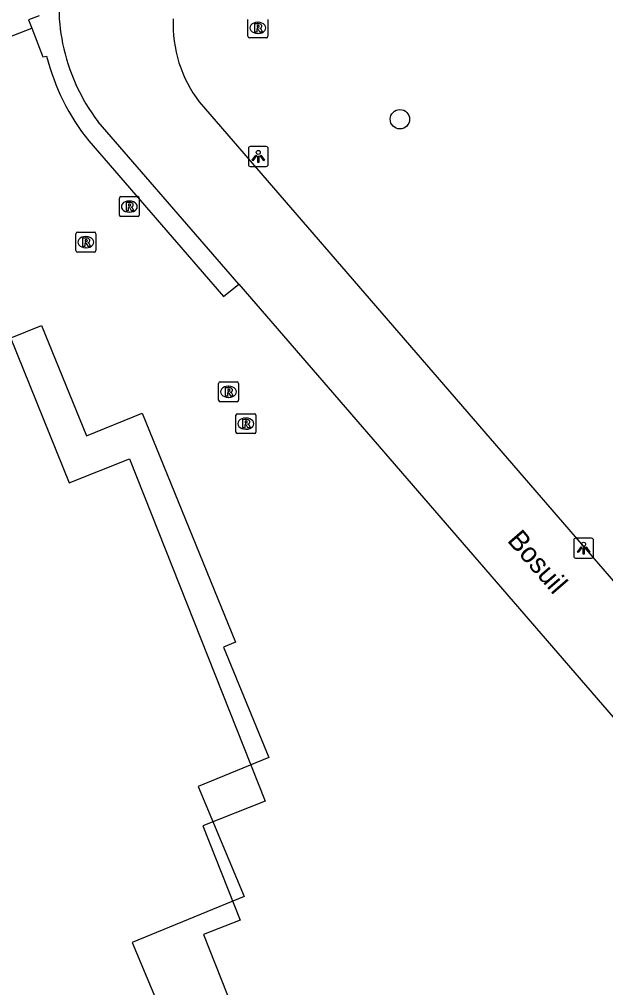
# Model space of a CAD drawing. Extents: x 156664 to 157568, y 383571 to 384421.
# Drawn here: x 156811.21 to 156840.66, y 383832.57 to 383881.24 of the extents above; entities that cross this region are included whole.
import ezdxf

# ---------------------------------------------------------------- set-up
doc = ezdxf.new("R2010")
doc.units = 0
for name, color, linetype in [('IMGEO_Berm_open', 7, 'Continuous'), ('IMGEO_Boom', 7, 'Continuous'), ('IMGEO_Groenvoorziening', 7, 'Continuous'), ('IMGEO_Lichtpunt', 7, 'Continuous'), ('IMGEO_Openbare_ruimte_label', 7, 'Continuous'), ('IMGEO_Pand', 7, 'Continuous'), ('IMGEO_Pand_vergunning_verleend', 7, 'Continuous'), ('IMGEO_Rijbaan_lokaal_open', 7, 'Continuous'), ('IMGEO_Rioolput', 7, 'Continuous')]:
    doc.layers.add(name, color=color, linetype=linetype)

msp = doc.modelspace()

# ---------------------------------------------------------------- linework, layer by layer
at = {"layer": 'IMGEO_Berm_open'}
for points in [[(156812.204, 383881.419), (156811.669, 383881.211), (156811.831, 383880.795)], [(156811.831, 383880.795), (156812.391, 383879.356), (156812.577, 383879.388)], [(156814.702, 383875.125), (156821.46, 383867.3), (156822.231, 383867.92)]]:
    msp.add_lwpolyline(points, dxfattribs=at)
msp.add_arc((156823.408, 383882.126), 11.171, 194.1855, 218.8047, dxfattribs=at)
at = {"layer": 'IMGEO_Boom'}
msp.add_circle((156830.325, 383876.218), 0.489, dxfattribs=at)
at = {"layer": 'IMGEO_Groenvoorziening'}
msp.add_lwpolyline([(156804.978, 383878.126), (156811.831, 383880.795)], dxfattribs=at)
at = {"layer": 'IMGEO_Lichtpunt'}
for p, q in [((156822.713, 383874.751), (156822.713, 383873.944)), ((156822.713, 383874.751), (156822.713, 383873.944)), ((156823.615, 383874.846), (156822.807, 383874.846)), ((156823.615, 383874.846), (156822.807, 383874.846)), ((156823.709, 383873.944), (156823.709, 383874.751)), ((156823.709, 383873.944), (156823.709, 383874.751)), ((156822.807, 383873.85), (156823.615, 383873.85)), ((156822.807, 383873.85), (156823.615, 383873.85)), ((156839.957, 383855.156), (156839.149, 383855.156)), ((156839.957, 383855.156), (156839.149, 383855.156)), ((156839.055, 383855.061), (156839.055, 383854.254)), ((156839.055, 383855.061), (156839.055, 383854.254)), ((156840.051, 383854.254), (156840.051, 383855.061)), ((156840.051, 383854.254), (156840.051, 383855.061)), ((156839.149, 383854.16), (156839.957, 383854.16)), ((156839.149, 383854.16), (156839.957, 383854.16))]:
    msp.add_line(p, q, dxfattribs=at)
for points in [[(156823.087, 383874.415), (156823.126, 383874.387), (156822.938, 383874.125), (156822.9, 383874.152), (156823.087, 383874.415)], [(156823.189, 383874.367), (156823.236, 383874.367), (156823.236, 383874.045), (156823.189, 383874.045), (156823.189, 383874.367)], [(156823.299, 383874.387), (156823.337, 383874.414), (156823.524, 383874.152), (156823.485, 383874.124), (156823.299, 383874.387)], [(156839.429, 383854.725), (156839.468, 383854.697), (156839.28, 383854.435), (156839.242, 383854.462), (156839.429, 383854.725)], [(156839.531, 383854.677), (156839.578, 383854.677), (156839.578, 383854.355), (156839.531, 383854.355), (156839.531, 383854.677)], [(156839.641, 383854.697), (156839.679, 383854.724), (156839.866, 383854.462), (156839.827, 383854.434), (156839.641, 383854.697)]]:
    msp.add_lwpolyline(points, dxfattribs=at)
for centre in [(156823.212, 383874.549), (156839.554, 383854.859)]:
    msp.add_circle(centre, 0.0994, dxfattribs=at)
for centre, start, end in [((156822.807, 383874.751), 90, 180), ((156822.807, 383874.751), 90, 180), ((156823.615, 383874.751), 0, 90), ((156823.615, 383874.751), 0, 90), ((156822.807, 383873.944), 180, 270), ((156822.807, 383873.944), 180, 270), ((156823.615, 383873.944), 270, 0), ((156823.615, 383873.944), 270, 360), ((156839.149, 383855.061), 90, 180), ((156839.149, 383855.061), 90, 180), ((156839.957, 383855.061), 0, 90), ((156839.957, 383855.061), 0, 90), ((156839.149, 383854.254), 180, 270), ((156839.149, 383854.254), 180, 270), ((156839.957, 383854.254), 270, 0), ((156839.957, 383854.254), 270, 360)]:
    msp.add_arc(centre, 0.0946, start, end, dxfattribs=at)
at = {"layer": 'IMGEO_Pand'}
msp.add_lwpolyline([(156810.752, 383865.212), (156812.318, 383865.856), (156814.59, 383860.304), (156817.377, 383861.45), (156822.064, 383849.936), (156821.462, 383849.689), (156823.742, 383844.139), (156820.198, 383842.684), (156822.503, 383837.144), (156816.871, 383834.832), (156818.054, 383832.045), (156811.056, 383829.074)], dxfattribs=at)
at = {"layer": 'IMGEO_Pand_vergunning_verleend'}
msp.add_lwpolyline([(156780.469, 383854.207), (156810.422, 383866.069), (156813.706, 383857.943), (156816.747, 383859.147), (156823.563, 383841.936), (156820.432, 383840.696), (156822.305, 383835.967), (156820.454, 383835.234), (156822.799, 383829.314), (156801.042, 383820.698), (156799.834, 383823.747), (156795.744, 383822.127), (156793.475, 383827.857), (156790.011, 383826.485), (156783.663, 383842.517), (156784.904, 383843.008), (156780.469, 383854.207)], dxfattribs=at)
at = {"layer": 'IMGEO_Rijbaan_lokaal_open'}
for points in [[(156820.249, 383877.085), (156862.917, 383827.693), (156866.643, 383823.379), (156904.906, 383779.134), (156906.372, 383777.464)], [(156822.231, 383867.92), (156815.167, 383876.091)], [(156822.231, 383867.92), (156859.631, 383824.659), (156863.331, 383820.379), (156901.778, 383775.877), (156902.832, 383774.643)]]:
    msp.add_lwpolyline(points, dxfattribs=at)
for centre, radius, start, end in [((156822.961, 383881.977), 9.772, 179.9847, 191.4947), ((156825.375, 383880.993), 6.446, 177.6397, 217.3168), ((156822.9, 383881.962), 9.71, 191.4781, 217.2058)]:
    msp.add_arc(centre, radius, start, end, dxfattribs=at)
at = {"layer": 'IMGEO_Rioolput'}
for p, q in [((156822.689, 383880.385), (156822.689, 383881.237)), ((156823.177, 383881.091), (156823.202, 383881.091)), ((156823.69, 383881.237), (156823.69, 383880.385)), ((156823.2, 383880.531), (156823.175, 383880.531)), ((156823.616, 383880.311), (156822.764, 383880.311)), ((156816.233, 383871.401), (156816.233, 383872.253)), ((156816.308, 383872.327), (156817.16, 383872.327)), ((156817.234, 383872.253), (156817.234, 383871.401)), ((156816.721, 383872.107), (156816.746, 383872.107)), ((156817.16, 383871.327), (156816.308, 383871.327)), ((156816.744, 383871.547), (156816.719, 383871.547)), ((156814.052, 383869.613), (156814.052, 383870.465)), ((156814.127, 383870.539), (156814.979, 383870.539)), ((156814.54, 383870.319), (156814.565, 383870.319)), ((156815.053, 383870.465), (156815.053, 383869.613)), ((156814.563, 383869.759), (156814.538, 383869.759)), ((156814.979, 383869.539), (156814.127, 383869.539)), ((156821.219, 383862.091), (156821.219, 383862.943)), ((156821.294, 383863.017), (156822.146, 383863.017)), ((156822.22, 383862.943), (156822.22, 383862.091)), ((156821.707, 383862.797), (156821.732, 383862.797)), ((156822.146, 383862.017), (156821.294, 383862.017)), ((156821.73, 383862.237), (156821.705, 383862.237)), ((156822.087, 383860.492), (156822.087, 383861.344)), ((156822.162, 383861.418), (156823.014, 383861.418)), ((156822.575, 383861.198), (156822.6, 383861.198)), ((156823.088, 383861.344), (156823.088, 383860.492)), ((156822.598, 383860.638), (156822.573, 383860.638)), ((156823.014, 383860.418), (156822.162, 383860.418))]:
    msp.add_line(p, q, dxfattribs=at)
for points in [[(156822.689, 383880.385), (156822.689, 383881.237)], [(156823.278, 383881.009), (156823.026, 383881.011), (156823.026, 383880.611)], [(156823.204, 383880.93), (156823.15, 383880.93), (156823.15, 383880.849)], [(156823.69, 383881.237), (156823.69, 383880.385)], [(156823.026, 383880.611), (156823.15, 383880.611), (156823.15, 383880.773), (156823.161, 383880.773)], [(156823.15, 383880.849), (156823.202, 383880.849)], [(156823.208, 383880.744), (156823.279, 383880.611), (156823.419, 383880.611), (156823.354, 383880.737)], [(156823.616, 383880.311), (156822.764, 383880.311)], [(156816.233, 383871.401), (156816.233, 383872.253)], [(156816.308, 383872.327), (156817.16, 383872.327)], [(156817.234, 383872.253), (156817.234, 383871.401)], [(156816.822, 383872.025), (156816.57, 383872.027), (156816.57, 383871.627)], [(156816.57, 383871.627), (156816.694, 383871.627), (156816.694, 383871.789), (156816.705, 383871.789)], [(156816.748, 383871.946), (156816.694, 383871.946), (156816.694, 383871.865)], [(156816.694, 383871.865), (156816.746, 383871.865)], [(156816.752, 383871.76), (156816.823, 383871.627), (156816.963, 383871.627), (156816.898, 383871.753)], [(156817.16, 383871.327), (156816.308, 383871.327)], [(156814.052, 383869.613), (156814.052, 383870.465)], [(156814.127, 383870.539), (156814.979, 383870.539)], [(156814.641, 383870.237), (156814.389, 383870.239), (156814.389, 383869.839)], [(156815.053, 383870.465), (156815.053, 383869.613)], [(156814.389, 383869.839), (156814.513, 383869.839), (156814.513, 383870.001), (156814.524, 383870.001)], [(156814.567, 383870.158), (156814.513, 383870.158), (156814.513, 383870.077)], [(156814.513, 383870.077), (156814.565, 383870.077)], [(156814.571, 383869.972), (156814.642, 383869.839), (156814.782, 383869.839), (156814.717, 383869.965)], [(156814.979, 383869.539), (156814.127, 383869.539)], [(156821.219, 383862.091), (156821.219, 383862.943)], [(156821.294, 383863.017), (156822.146, 383863.017)], [(156822.22, 383862.943), (156822.22, 383862.091)], [(156821.808, 383862.715), (156821.556, 383862.717), (156821.556, 383862.317)], [(156821.556, 383862.317), (156821.68, 383862.317), (156821.68, 383862.479), (156821.691, 383862.479)], [(156821.734, 383862.636), (156821.68, 383862.636), (156821.68, 383862.555)], [(156821.68, 383862.555), (156821.732, 383862.555)], [(156821.738, 383862.45), (156821.809, 383862.317), (156821.949, 383862.317), (156821.884, 383862.443)], [(156822.146, 383862.017), (156821.294, 383862.017)], [(156822.087, 383860.492), (156822.087, 383861.344)], [(156822.162, 383861.418), (156823.014, 383861.418)], [(156822.676, 383861.116), (156822.424, 383861.118), (156822.424, 383860.718)], [(156822.602, 383861.037), (156822.548, 383861.037), (156822.548, 383860.956)], [(156823.088, 383861.344), (156823.088, 383860.492)], [(156822.424, 383860.718), (156822.548, 383860.718), (156822.548, 383860.88), (156822.559, 383860.88)], [(156822.548, 383860.956), (156822.6, 383860.956)], [(156822.606, 383860.851), (156822.677, 383860.718), (156822.817, 383860.718), (156822.752, 383860.844)], [(156823.014, 383860.418), (156822.162, 383860.418)]]:
    msp.add_lwpolyline(points, dxfattribs=at)
for centre, radius, start, end in [((156823.21, 383880.834), 0.0964, 77.0061, 93.1865), ((156823.224, 383880.891), 0.0378, 276.6634, 79.6772), ((156823.277, 383880.899), 0.109, 350.3612, 89.416), ((156823.16, 383880.72), 0.0533, 26.0293, 88.6989), ((156823.186, 383881.038), 0.19, 274.7715, 282.9687), ((156823.275, 383880.899), 0.112, 277.5842, 350.9817), ((156823.259, 383880.684), 0.108, 29.5134, 73.7905), ((156822.766, 383880.387), 0.0765, 181.552, 268.448), ((156822.766, 383880.387), 0.0765, 181.552, 268.448), ((156823.614, 383880.387), 0.0765, 271.552, 358.448), ((156823.614, 383880.387), 0.0765, 271.552, 358.448), ((156816.31, 383872.251), 0.0765, 91.552, 178.448), ((156816.31, 383872.251), 0.0765, 91.552, 178.448), ((156817.158, 383872.251), 0.0765, 1.552, 88.448), ((156817.158, 383872.251), 0.0765, 1.552, 88.448), ((156816.704, 383871.736), 0.0533, 26.0293, 88.6989), ((156816.73, 383872.054), 0.19, 274.7715, 282.9687), ((156816.754, 383871.85), 0.0964, 77.0061, 93.1865), ((156816.768, 383871.907), 0.0378, 276.6634, 79.6772), ((156816.821, 383871.915), 0.109, 350.3612, 89.416), ((156816.819, 383871.915), 0.112, 277.5842, 350.9817), ((156816.803, 383871.7), 0.108, 29.5134, 73.7905), ((156816.31, 383871.403), 0.0765, 181.552, 268.448), ((156816.31, 383871.403), 0.0765, 181.552, 268.448), ((156817.158, 383871.403), 0.0765, 271.552, 358.448), ((156817.158, 383871.403), 0.0765, 271.552, 358.448), ((156814.129, 383870.463), 0.0765, 91.552, 178.448), ((156814.129, 383870.463), 0.0765, 91.552, 178.448), ((156814.64, 383870.127), 0.109, 350.3612, 89.416), ((156814.977, 383870.463), 0.0765, 1.552, 88.448), ((156814.977, 383870.463), 0.0765, 1.552, 88.448), ((156814.523, 383869.948), 0.0533, 26.0293, 88.6989), ((156814.549, 383870.266), 0.19, 274.7715, 282.9687), ((156814.573, 383870.062), 0.0964, 77.0061, 93.1865), ((156814.587, 383870.119), 0.0378, 276.6634, 79.6772), ((156814.638, 383870.127), 0.112, 277.5842, 350.9817), ((156814.622, 383869.912), 0.108, 29.5134, 73.7905), ((156814.129, 383869.615), 0.0765, 181.552, 268.448), ((156814.129, 383869.615), 0.0765, 181.552, 268.448), ((156814.977, 383869.615), 0.0765, 271.552, 358.448), ((156814.977, 383869.615), 0.0765, 271.552, 358.448), ((156821.296, 383862.941), 0.0765, 91.552, 178.448), ((156821.296, 383862.941), 0.0765, 91.552, 178.448), ((156822.144, 383862.941), 0.0765, 1.552, 88.448), ((156822.144, 383862.941), 0.0765, 1.552, 88.448), ((156821.69, 383862.426), 0.0533, 26.0293, 88.6989), ((156821.716, 383862.744), 0.19, 274.7715, 282.9687), ((156821.74, 383862.54), 0.0964, 77.0061, 93.1865), ((156821.754, 383862.597), 0.0378, 276.6634, 79.6772), ((156821.807, 383862.605), 0.109, 350.3612, 89.416), ((156821.805, 383862.605), 0.112, 277.5842, 350.9817), ((156821.789, 383862.39), 0.108, 29.5134, 73.7905), ((156821.296, 383862.093), 0.0765, 181.552, 268.448), ((156821.296, 383862.093), 0.0765, 181.552, 268.448), ((156822.144, 383862.093), 0.0765, 271.552, 358.448), ((156822.144, 383862.093), 0.0765, 271.552, 358.448), ((156822.164, 383861.342), 0.0765, 91.552, 178.448), ((156822.164, 383861.342), 0.0765, 91.552, 178.448), ((156822.608, 383860.941), 0.0964, 77.0061, 93.1865), ((156822.622, 383860.998), 0.0378, 276.6634, 79.6772), ((156822.675, 383861.006), 0.109, 350.3612, 89.416), ((156822.673, 383861.006), 0.112, 277.5842, 350.9817), ((156823.012, 383861.342), 0.0765, 1.552, 88.448), ((156823.012, 383861.342), 0.0765, 1.552, 88.448), ((156822.164, 383860.494), 0.0765, 181.552, 268.448), ((156822.164, 383860.494), 0.0765, 181.552, 268.448), ((156822.558, 383860.827), 0.0533, 26.0293, 88.6989), ((156822.584, 383861.145), 0.19, 274.7715, 282.9687), ((156822.657, 383860.791), 0.108, 29.5134, 73.7905), ((156823.012, 383860.494), 0.0765, 271.552, 358.448), ((156823.012, 383860.494), 0.0765, 271.552, 358.448)]:
    msp.add_arc(centre, radius, start, end, dxfattribs=at)
for centre, major_axis, ratio, start_param, end_param in [((156823.176, 383880.811), (-0.387, 0.002), 0.722429, 4.712389, 7.853982), ((156823.201, 383880.811), (-0.39, 0.002), 0.717154, 1.570796, 4.712389), ((156816.72, 383871.827), (-0.387, 0.002), 0.722429, 4.712389, 7.853982), ((156816.745, 383871.827), (-0.39, 0.002), 0.717154, 1.570796, 4.712389), ((156814.539, 383870.039), (-0.387, 0.002), 0.722429, 4.712389, 7.853982), ((156814.564, 383870.039), (-0.39, 0.002), 0.717154, 1.570796, 4.712389), ((156821.706, 383862.517), (-0.387, 0.002), 0.722429, 4.712389, 7.853982), ((156821.731, 383862.517), (-0.39, 0.002), 0.717154, 1.570796, 4.712389), ((156822.574, 383860.918), (-0.387, 0.002), 0.722429, 4.712389, 7.853982), ((156822.599, 383860.918), (-0.39, 0.002), 0.717154, 1.570796, 4.712389)]:
    msp.add_ellipse(centre, major_axis=major_axis, ratio=ratio, start_param=start_param, end_param=end_param, dxfattribs=at)

# ---------------------------------------------------------------- texts
at = {"layer": 'IMGEO_Openbare_ruimte_label'}
msp.add_text('Bosuil', height=1, rotation=310.8624, dxfattribs=at).set_placement((156835.677, 383855.029))

doc.saveas('drawing.dxf')
